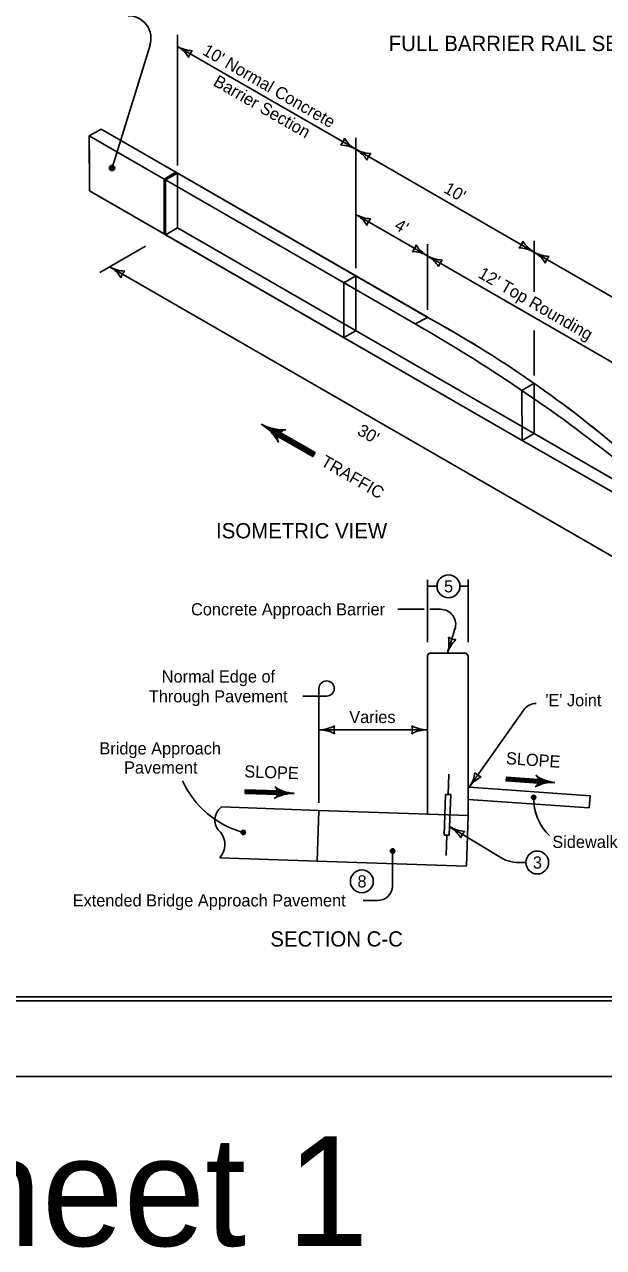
# Model space of a CAD drawing. Extents: x 10028 to 81668, y 6395 to 11634.
# Drawn here: x 11525 to 12284, y 7600 to 9205 of the extents above; entities that cross this region are included whole.
import ezdxf

# ---------------------------------------------------------------- set-up
doc = ezdxf.new("R2010")
doc.units = 0
for name, color, linetype in [('Default', 7, 'Continuous'), ('dsnCellElements', 7, 'Continuous'), ('dsnstdblockInterim', 7, 'Continuous'), ('dsnStdDimension', 7, 'Continuous'), ('dsnStdTextLabel', 7, 'Continuous'), ('ShtPlotIdentification', 7, 'Continuous')]:
    doc.layers.add(name, color=color, linetype=linetype)

msp = doc.modelspace()

# ---------------------------------------------------------------- linework, layer by layer
at = {"layer": 'Default'}
msp.add_lwpolyline([(10132.5, 9944), (13267.5, 9944), (13267.5, 7924), (10132.5, 7924)], close=True, dxfattribs=at)
msp.add_lwpolyline([(10132.5, 9944), (13267.5, 9944), (13267.5, 7924), (10132.5, 7924)], close=True, dxfattribs=at)
at = {"layer": 'dsnCellElements'}
for p, q in [((11609.6, 9059.2), (11625.2, 9068.2)), ((11609.7, 9023.1), (11609.6, 9059.2)), ((11625.2, 9068.2), (12052.5, 8821.5)), ((11609.8, 8987), (11609.7, 9023.1)), ((12177.4, 8659.3), (11609.8, 8987)), ((11609.8, 8987), (11609.8, 8987)), ((12412.1, 8525), (12177.4, 8659.3)), ((12057.7, 8380.4), (12101.5, 8380.4))]:
    msp.add_line(p, q, dxfattribs=at)
msp.add_lwpolyline([(12106.5, 8376), (12106.5, 8167), (12052.9, 8168.9), (12052.9, 8374.8)], dxfattribs=at)
for centre, radius, start, end in [((11332.1, 7502.2), 1503.1, 49.0293, 61.3631), ((12057.9, 8375.4), 5, 91.6206, 186.0094), ((12101.5, 8375.4), 5, 7.7246, 90)]:
    msp.add_arc(centre, radius, start, end, dxfattribs=at)
at = {"layer": 'dsnstdblockInterim'}
for points in [[(10132.5, 9944), (13267.5, 9944), (13267.5, 7924), (10132.5, 7924)], [(10132.5, 9939), (13267.5, 9939), (13267.5, 7929), (10132.5, 7929)]]:
    msp.add_lwpolyline(points, close=True, dxfattribs=at)
at = {"layer": 'dsnStdDimension'}
msp.add_lwpolyline([(10028, 7824.5), (13372, 7824.5), (13372, 10408.5), (10028, 10408.5)], close=True, dxfattribs=at)
at = {"layer": 'ShtPlotIdentification'}
for p, q in [((11725.2, 9191.7), (11725.2, 9020.4)), ((11639.4, 9017.2), (11689.2, 9178.1)), ((11959, 9041.7), (11725.2, 9176.7)), ((11609.6, 9059.2), (11625.2, 9068.2)), ((11707.7, 9002.6), (11609.6, 9059.2)), ((11609.6, 9059.2), (11609.8, 8987)), ((11723.2, 9011.6), (11625.2, 9068.2)), ((11959, 9056.7), (11959, 8885.4)), ((12192.8, 8906.6), (11959, 9041.7)), ((11707.7, 9002.6), (11723.2, 9011.6)), ((11709.6, 9001.4), (11725.2, 9010.4)), ((11725.2, 9010.4), (11725.2, 8938.4)), ((12052.5, 8821.4), (11725.2, 9010.4)), ((11707.7, 9002.6), (11707.8, 8930.5)), ((12037, 8812.4), (11709.6, 9001.4)), ((11709.6, 9001.4), (11709.6, 8929.4)), ((11707.8, 8930.5), (11609.8, 8987)), ((12052.9, 8901.9), (11959, 8956.1)), ((11725.2, 8938.4), (11709.6, 8929.4)), ((12177.4, 8659.3), (11709.6, 8929.4)), ((12192.8, 8668.4), (11725.2, 8938.4)), ((11683.2, 8914.4), (11623.4, 8879.9)), ((12052.9, 8916.9), (12052.9, 8830.8)), ((12192.8, 8921.6), (12192.8, 8854.3)), ((12317.6, 8749), (12052.9, 8901.9)), ((12426.7, 8771.6), (12192.8, 8906.6)), ((12338.1, 8482.3), (11636.4, 8887.4)), ((11959, 8875.4), (11943.4, 8866.4)), ((11943.4, 8866.4), (11943.4, 8794.4)), ((11959, 8803.4), (11959, 8875.4)), ((12037, 8812.4), (12052.9, 8820.8)), ((11959, 8803.4), (11943.4, 8794.4)), ((12192.8, 8803.7), (12192.8, 8744.5)), ((12176.8, 8725.2), (12192.8, 8734.5)), ((12192.8, 8734.5), (12192.8, 8668.4)), ((12176.8, 8725.2), (12177.3, 8659.4)), ((11860, 8670.2), (11860, 8670.2)), ((11856.9, 8664.8), (11856.9, 8664.8)), ((11858.3, 8667.5), (11904.2, 8640.9)), ((12192.8, 8668.4), (12177.3, 8659.4)), ((12177.4, 8659.3), (12412.1, 8525)), ((12426.7, 8533.4), (12192.8, 8668.4)), ((12052.9, 8394.5), (12052.9, 8476.6)), ((12065.6, 8468), (12052.9, 8468)), ((12106.5, 8468), (12095.6, 8468)), ((12106.5, 8394.5), (12106.5, 8476.8)), ((12014.4, 8437.8), (12048.6, 8437.8)), ((12056.3, 8437.8), (12070.1, 8437.8)), ((12079.2, 8380.2), (12089.1, 8411.6)), ((12052.9, 8168.9), (12052.9, 8375.9)), ((12101.5, 8380.4), (12057.8, 8380.4)), ((12106.5, 8167), (12106.5, 8375.9)), ((11910.8, 8317.8), (11910.8, 8333.8)), ((11904.8, 8323.8), (11889.4, 8323.8)), ((11920.8, 8323.8), (11904.8, 8323.8)), ((11910.8, 8183.8), (11910.8, 8317.8)), ((12107.8, 8204.2), (12179.3, 8305.7)), ((12052.9, 8279.6), (11910.8, 8279.6)), ((12081.2, 8221.3), (12080.2, 8194.6)), ((12266.3, 8193.1), (12107.8, 8204.2)), ((12198.6, 8212), (12156.3, 8215)), ((12198.3, 8209.5), (12198.3, 8209.5)), ((12198.7, 8214.4), (12198.7, 8214.4)), ((11856.5, 8197), (11814.1, 8198.4)), ((11856.3, 8194.4), (11856.3, 8194.4)), ((11856.5, 8199.4), (11856.5, 8199.4)), ((12076.9, 8194.7), (12075, 8141.4)), ((12076.9, 8194.7), (12083.6, 8194.5)), ((12083.6, 8194.5), (12081.7, 8141.2)), ((12265.1, 8177.2), (12106.6, 8188.2)), ((12266.3, 8193.1), (12265.1, 8177.2)), ((11910.8, 8173.8), (11783.1, 8178.3)), ((11908.5, 8107.2), (11910.8, 8173.8)), ((12106.5, 8167), (11910.8, 8173.8)), ((12053.2, 8168.9), (12106.5, 8167)), ((12104.1, 8100.4), (12106.5, 8167)), ((12075, 8141.4), (12081.7, 8141.2)), ((12078.4, 8141.3), (12077.4, 8114.7)), ((12082.1, 8152.5), (12146.1, 8113.6)), ((11908.5, 8107.2), (11780.7, 8111.7)), ((12007.3, 8120.4), (12007.3, 8074.5)), ((12104.1, 8100.4), (11908.5, 8107.2)), ((12173, 8105.4), (12182, 8105.4)), ((11968.7, 8055.7), (11987.4, 8055.7))]:
    msp.add_line(p, q, dxfattribs=at)
for points in [[(11639.1, 9014), (11640.3, 9014.5), (11642.1, 9015.1), (11642.5, 9016.9), (11642.2, 9018.6), (11641, 9020.1), (11639.3, 9019.9), (11637.4, 9019.7), (11636.6, 9018.2), (11636.4, 9016.7), (11637.5, 9014.6), (11638.8, 9014.5), (11640.7, 9014.9), (11642.2, 9016.1), (11642.1, 9017.8), (11641, 9019.3), (11639.3, 9019.4), (11637.5, 9019.1), (11637.2, 9018), (11636.8, 9016.8), (11637.7, 9015.2), (11639, 9015.3), (11640.5, 9015.5), (11641.7, 9016.4), (11641.1, 9017.9), (11639.9, 9018.8), (11638.4, 9018.9), (11638, 9018), (11637.5, 9017.1), (11638.3, 9015.9), (11639.4, 9015.6), (11640.4, 9016.2), (11640.5, 9017.3), (11640, 9018.1), (11638.9, 9018.4), (11638.4, 9017.9), (11638.1, 9017.3), (11638.7, 9016.4), (11639.4, 9016.2), (11640.1, 9016.7), (11640, 9017.3), (11639.5, 9017.7), (11638.7, 9017.6), (11638.8, 9017.1), (11639.4, 9016.8)], [(11863, 8672.7), (11859.3, 8670.7), (11856.5, 8666.3), (11855.8, 8661.4), (11850.7, 8668.1), (11844.1, 8675), (11842.2, 8676.8), (11848.6, 8674.6), (11858.5, 8672.7), (11861.8, 8672.6), (11855.3, 8663.5), (11845.4, 8674.7), (11859.5, 8671.4), (11855.2, 8665), (11848.6, 8672.9), (11857.4, 8670.4), (11855.5, 8666.3), (11851.1, 8671.1), (11855.9, 8669.9), (11855, 8668), (11853.4, 8669.7)], [(11859.9, 8670), (11905.7, 8643.5), (11902.7, 8638.3), (11856.9, 8664.8), (11859.6, 8669.2), (11904.8, 8643.3), (11902.3, 8639.2), (11858.2, 8664.9), (11859.9, 8668.1), (11903.8, 8643), (11902, 8640.3), (11859.1, 8665.1), (11860.1, 8667.1), (11902.9, 8642.7), (11902, 8641.2), (11860.1, 8665.4)], [(12198.4, 8209.6), (12156.1, 8212.6), (12156.5, 8217.4), (12198.7, 8214.4), (12198.3, 8210.3), (12156.7, 8213.1), (12157.1, 8216.9), (12197.7, 8213.9), (12197.7, 8211), (12157.3, 8213.7), (12157.6, 8216.2), (12197.2, 8213.4), (12197.2, 8211.6), (12157.9, 8214.2), (12158, 8215.6), (12196.6, 8212.8)], [(12197, 8206.6), (12199, 8209.3), (12199.5, 8213.5), (12198.2, 8217.2), (12204.3, 8214.2), (12211.5, 8211.6), (12213.5, 8211), (12208.1, 8210.3), (12200.3, 8208.2), (12197.9, 8207.1), (12199.4, 8215.9), (12210.4, 8211.3), (12199.1, 8208.8), (12200, 8214.9), (12207.5, 8211.5), (12200.3, 8210.2), (12200.2, 8213.8), (12205, 8211.9), (12201.2, 8211.1), (12201.1, 8212.8), (12202.9, 8212.1)], [(11856.4, 8194.6), (11814, 8196), (11814.2, 8200.8), (11856.5, 8199.4), (11856.2, 8195.3), (11814.6, 8196.6), (11814.8, 8200.4), (11855.6, 8198.8), (11855.6, 8195.9), (11815.2, 8197.2), (11815.4, 8199.7), (11855, 8198.3), (11855.1, 8196.5), (11815.7, 8197.7), (11815.8, 8199.1), (11854.5, 8197.7)], [(11855.1, 8191.5), (11857, 8194.3), (11857.4, 8198.5), (11856, 8202.2), (11862.1, 8199.4), (11869.4, 8197), (11871.4, 8196.4), (11866.1, 8195.6), (11858.3, 8193.2), (11856, 8192), (11857.1, 8200.9), (11868.3, 8196.7), (11857.1, 8193.7), (11857.8, 8199.9), (11865.4, 8196.7), (11858.3, 8195.2), (11858.1, 8198.8), (11862.9, 8197), (11859.1, 8196.1), (11859, 8197.8), (11860.8, 8197.2)], [(12192, 8188.2), (12193, 8188.7), (12194.4, 8189.1), (12194.7, 8190.6), (12194.5, 8191.9), (12193.6, 8193.1), (12192.2, 8193), (12190.7, 8192.8), (12190, 8191.6), (12189.9, 8190.4), (12190.7, 8188.8), (12191.8, 8188.6), (12193.3, 8189), (12194.5, 8190), (12194.4, 8191.4), (12193.5, 8192.5), (12192.2, 8192.6), (12190.7, 8192.3), (12190.5, 8191.5), (12190.2, 8190.5), (12190.9, 8189.3), (12191.9, 8189.3), (12193.2, 8189.5), (12194.1, 8190.2), (12193.6, 8191.4), (12192.7, 8192.1), (12191.4, 8192.2), (12191.1, 8191.5), (12190.8, 8190.8), (12191.4, 8189.8), (12192.3, 8189.6), (12193.1, 8190), (12193.1, 8190.9), (12192.7, 8191.5), (12191.9, 8191.8), (12191.5, 8191.4), (12191.2, 8190.9), (12191.7, 8190.2), (12192.3, 8190.1), (12192.8, 8190.4), (12192.7, 8190.9), (12192.3, 8191.2), (12191.7, 8191.2), (12191.7, 8190.8), (12192.2, 8190.5)], [(11811.3, 8142.3), (11812.2, 8142.7), (11813.7, 8143.2), (11814, 8144.7), (11813.8, 8146), (11812.9, 8147.2), (11811.5, 8147.1), (11810, 8146.9), (11809.3, 8145.7), (11809.2, 8144.4), (11810, 8142.8), (11811.1, 8142.7), (11812.6, 8143.1), (11813.8, 8144), (11813.7, 8145.4), (11812.8, 8146.5), (11811.5, 8146.7), (11810, 8146.4), (11809.8, 8145.5), (11809.5, 8144.5), (11810.2, 8143.3), (11811.2, 8143.4), (11812.5, 8143.6), (11813.4, 8144.2), (11812.9, 8145.5), (11812, 8146.2), (11810.7, 8146.2), (11810.4, 8145.6), (11810, 8144.8), (11810.6, 8143.8), (11811.6, 8143.6), (11812.4, 8144), (11812.4, 8144.9), (11812, 8145.6), (11811.2, 8145.8), (11810.8, 8145.5), (11810.5, 8145), (11811, 8144.2), (11811.5, 8144.1), (11812.1, 8144.4), (11812, 8144.9), (11811.6, 8145.3), (11811, 8145.2), (11811, 8144.8), (11811.5, 8144.6)], [(12007, 8118.1), (12008, 8118.5), (12009.5, 8118.9), (12009.7, 8120.4), (12009.5, 8121.7), (12008.6, 8123), (12007.2, 8122.8), (12005.7, 8122.6), (12005, 8121.4), (12004.9, 8120.2), (12005.8, 8118.6), (12006.8, 8118.5), (12008.3, 8118.8), (12009.5, 8119.8), (12009.5, 8121.2), (12008.5, 8122.3), (12007.2, 8122.4), (12005.7, 8122.1), (12005.5, 8121.3), (12005.2, 8120.3), (12005.9, 8119.1), (12007, 8119.1), (12008.2, 8119.3), (12009.1, 8120), (12008.7, 8121.2), (12007.7, 8121.9), (12006.5, 8122), (12006.2, 8121.3), (12005.8, 8120.6), (12006.4, 8119.6), (12007.3, 8119.4), (12008.1, 8119.8), (12008.2, 8120.7), (12007.7, 8121.4), (12006.9, 8121.6), (12006.5, 8121.2), (12006.3, 8120.7), (12006.7, 8120), (12007.3, 8119.9), (12007.9, 8120.2), (12007.8, 8120.7), (12007.3, 8121), (12006.8, 8121), (12006.8, 8120.6), (12007.3, 8120.4)]]:
    msp.add_lwpolyline(points, dxfattribs=at)
for centre, radius in [((11639.4, 9017.2), 3.5), ((12080.6, 8468), 15), ((12192.2, 8190.8), 2.8), ((11811.5, 8144.9), 2.8), ((12007.3, 8120.6), 2.8), ((12197, 8105.4), 15), ((11967, 8080.6), 15)]:
    msp.add_circle(centre, radius, dxfattribs=at)
for centre, radius, start, end in [((11660.5, 9187), 30, 342.7953, 90), ((11746.4, 9213.5), 42.5, 239.9998, 268.0722), ((11703.9, 9139.8), 42.5, 31.9273, 59.9998), ((11746.4, 9213.5), 42.5, 239.9998, 268.0722), ((11703.9, 9139.8), 42.5, 31.9273, 59.9998), ((11756, 9158.8), 16.4, 132.2664, 167.7331), ((11756, 9158.8), 16.4, 132.2664, 167.7331), ((11928.2, 9059.5), 16.4, 312.2664, 347.7331), ((11928.2, 9059.5), 16.4, 312.2664, 347.7331), ((11980.3, 9078.5), 42.5, 211.9273, 239.9998), ((11980.3, 9078.5), 42.5, 211.9273, 239.9998), ((11937.8, 9004.8), 42.5, 59.9998, 88.0722), ((11937.8, 9004.8), 42.5, 59.9998, 88.0722), ((11980.3, 9078.5), 42.5, 239.9996, 268.0721), ((11937.8, 9004.8), 42.5, 31.9271, 59.9996), ((11980.3, 9078.5), 42.5, 239.9996, 268.0721), ((11937.8, 9004.8), 42.5, 31.9271, 59.9996), ((11989.9, 9023.8), 16.4, 132.2662, 167.7329), ((11989.9, 9023.8), 16.4, 132.2662, 167.7329), ((11980.3, 8992.9), 42.5, 239.9999, 268.0724), ((11937.8, 8919.3), 42.5, 31.9274, 59.9999), ((11980.3, 8992.9), 42.5, 239.9999, 268.0724), ((11937.8, 8919.3), 42.5, 31.9274, 59.9999), ((11989.9, 8938.3), 16.4, 132.2665, 167.7332), ((11989.9, 8938.3), 16.4, 132.2665, 167.7332), ((12022, 8919.7), 16.4, 312.2665, 347.7332), ((12022, 8919.7), 16.4, 312.2665, 347.7332), ((12074.1, 8938.7), 42.5, 211.9274, 239.9999), ((12074.1, 8938.7), 42.5, 211.9274, 239.9999), ((12162, 8924.5), 16.4, 312.2662, 347.7329), ((12162, 8924.5), 16.4, 312.2662, 347.7329), ((12171.6, 8869.8), 42.5, 59.9996, 88.0721), ((12171.6, 8869.8), 42.5, 59.9996, 88.0721), ((12214.1, 8943.5), 42.5, 211.9271, 239.9996), ((12214.1, 8943.5), 42.5, 211.9271, 239.9996), ((12031.6, 8865.1), 42.5, 59.9999, 88.0724), ((12031.6, 8865.1), 42.5, 59.9999, 88.0724), ((12074.1, 8938.7), 42.5, 239.9997, 268.0722), ((12031.6, 8865.1), 42.5, 31.9272, 59.9997), ((12083.8, 8884.1), 16.4, 132.2664, 167.7331), ((12214.1, 8943.5), 42.5, 239.9995, 268.072), ((12171.6, 8869.8), 42.5, 31.9271, 59.9995), ((12214.1, 8943.5), 42.5, 239.9995, 268.072), ((12171.6, 8869.8), 42.5, 31.9271, 59.9995), ((12223.7, 8888.8), 16.4, 132.2662, 167.7329), ((12223.7, 8888.8), 16.4, 132.2662, 167.7329), ((11657.7, 8924.2), 42.5, 239.9998, 268.0723), ((11615.2, 8850.6), 42.5, 31.9273, 59.9998), ((11667.3, 8869.6), 16.4, 132.2664, 167.7331), ((11332.1, 7502.2), 1503.1, 49.0301, 61.3606), ((10988.6, 6976.7), 2114, 51.502, 60.2695), ((11801.1, 8626.1), 64.5, 28.2857, 58.3158), ((11865.5, 8737.7), 64.5, 241.6842, 271.7143), ((11867.8, 8662), 11.3, 91.7147, 208.2853), ((12070.1, 8417.8), 20, 341.8709, 90), ((12038, 8393.2), 43.2, 342.4493, 10.5218), ((12120.4, 8367.2), 43.2, 134.3768, 162.4493), ((12090.1, 8414.7), 16.7, 234.7159, 270.1826), ((12057.9, 8375.4), 5, 90, 173.9906), ((12101.5, 8375.4), 5, 358, 90), ((11920.8, 8333.8), 10, 270, 180), ((12195.7, 8294.1), 20, 90, 144.806), ((11910.8, 8322.8), 43.2, 270, 298.0725), ((11947, 8279.6), 16.7, 162.2666, 197.7334), ((12016.7, 8279.6), 16.7, 342.2666, 17.7333), ((12052.9, 8322.8), 43.2, 241.9275, 270), ((11910.8, 8236.4), 43.2, 61.9275, 90), ((12052.9, 8236.4), 43.2, 90, 118.0725), ((12072.5, 8229.1), 43.2, 324.8061, 352.8786), ((12128.6, 8233.8), 16.7, 217.0727, 252.5394), ((11843.4, 8263.2), 122.5, 204.3091, 254.9009), ((11847.7, 8197.3), 9.03, 299.7144, 56.2851), ((11881.4, 8247.7), 51.6, 236.2855, 266.3155), ((12143, 8179.3), 43.2, 116.7336, 144.8061), ((12189.9, 8212.6), 9.03, 297.7136, 54.2843), ((12218.1, 8159), 51.6, 87.6832, 117.7132), ((12225.2, 8261.8), 51.6, 234.2847, 264.3147), ((11877.8, 8144.6), 51.6, 89.684, 119.714), ((12259.4, 8189.2), 67.2, 178.6576, 226.2027), ((11795, 8161.2), 20.8, 124.8321, 230.0377), ((11761.7, 8128.9), 25.7, 317.8283, 39.2857), ((12104.5, 8189.4), 43.2, 238.7208, 266.7932), ((12059.7, 8115.6), 43.2, 30.6483, 58.7208), ((12113, 8133.7), 16.7, 130.9874, 166.4541), ((12173, 8153.4), 48, 235.8571, 270), ((11988, 8075), 19.3, 268.4296, 358.4296)]:
    msp.add_arc(centre, radius, start, end, dxfattribs=at)

# ---------------------------------------------------------------- texts
at = {"layer": 'dsnCellElements'}
for s, height, p in [('FULL BARRIER RAIL SECTION', 20, (12002.3, 9170.6)), ('ISOMETRIC VIEW', 20, (11775.8, 8530.9)), ('Concrete Approach Barrier', 16, (11743, 8429.8)), ('Normal Edge of', 16, (11704.6, 8341.6)), ('Through Pavement', 16, (11687.7, 8315.6)), ("'E' Joint", 16, (12207.6, 8310.5)), ('Varies', 16, (11950.5, 8288.4)), ('Bridge Approach', 16, (11622.9, 8247.2)), ('Pavement', 16, (11655.2, 8222.1)), ('Sidewalk', 16, (12216.8, 8124.5)), ('Extended Bridge Approach Pavement', 16, (11587.8, 8047.7)), ('SECTION C-C', 20, (11847, 7995.1))]:
    msp.add_text(s, height=height, dxfattribs=at).set_placement(p)
for s, rotation, p in [("10' Normal Concrete", 330, (11756.7, 9166.8)), ('Barrier Section', 330, (11770.9, 9126.2)), ("10'", 330, (12073.2, 8985.7)), ("4'", 330, (12008.4, 8937.6)), ("12' Top Rounding", 330, (12118.2, 8874.2)), ("30'", 330, (11959.7, 8668)), ('TRAFFIC', 330, (11911.9, 8627.2)), ('SLOPE', 355.9992, (12155.6, 8234.6)), ('SLOPE', 358, (11812.7, 8217.2))]:
    msp.add_text(s, height=16, rotation=rotation, dxfattribs=at).set_placement(p)
at = {"layer": 'dsnStdTextLabel'}
msp.add_text('Sheet 1', height=144, dxfattribs=at).set_placement((11311.9, 7602))
at = {"layer": 'ShtPlotIdentification'}
for s, p in [('5', (12074.8, 8460)), ('3', (12191.3, 8097.4)), ('8', (11961.3, 8072.6))]:
    msp.add_text(s, height=16, dxfattribs=at).set_placement(p)

doc.saveas('drawing.dxf')
